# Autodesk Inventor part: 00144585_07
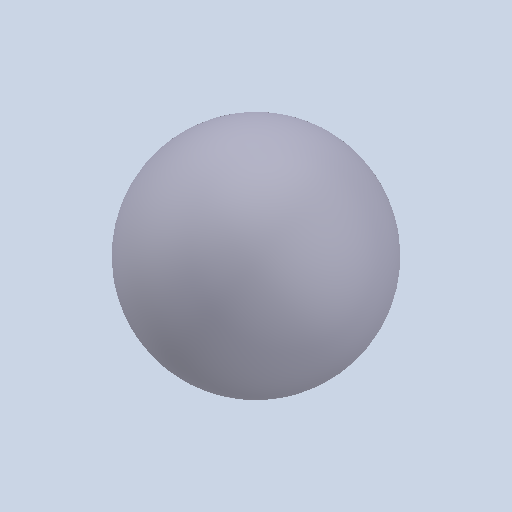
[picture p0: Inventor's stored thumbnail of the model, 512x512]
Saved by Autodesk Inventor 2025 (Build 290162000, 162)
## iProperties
Created: 2021-02
Part Number: 00144585_07
Material: Generico
Document SubType Name: Modeling
Designer: Ryzen5700u
Density: 1 g/cm^3
Appearance: Default
Author: Ryzen5700u
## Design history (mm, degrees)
feature "Solido1"
node "Solido2"
